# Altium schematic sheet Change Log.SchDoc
size 431 x 279 mm; Organization: ORGANIZATION; Address1: ADDRESS 1; Address2: ADDRESS 2; Address3: ADDRESS 3; Address4: ADDRESS 4; Revision: -; ENG_APP_DATE: --/--/--; DSN_APP_DATE: --/--/--; CHK_APP_DATE: --/--/--
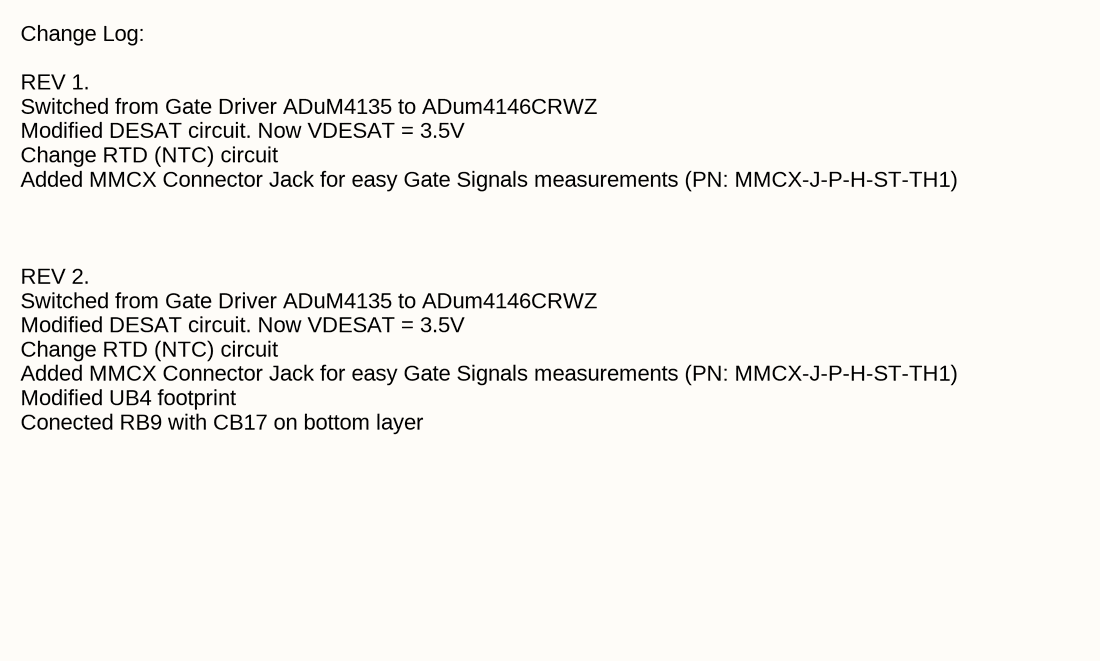
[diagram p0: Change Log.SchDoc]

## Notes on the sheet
- Change Log:
  REV 1.
  Switched from Gate Driver ADuM4135 to ADum4146CRWZ
  Modified DESAT circuit. Now VDESAT = 3.5V
  Change RTD (NTC) circuit
  Added MMCX Connector Jack for easy Gate Signals measurements (PN: MMCX-J-P-H-ST-TH1)
  REV 2.
  Switched from Gate Driver ADuM4135 to ADum4146CRWZ
  Modified DESAT circuit. Now VDESAT = 3.5V
  Change RTD (NTC) circuit
  Added MMCX Connector Jack for easy Gate Signals measurements (PN: MMCX-J-P-H-ST-TH1)
  Modified UB4 footprint
  Conected RB9 with CB17 on bottom layer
